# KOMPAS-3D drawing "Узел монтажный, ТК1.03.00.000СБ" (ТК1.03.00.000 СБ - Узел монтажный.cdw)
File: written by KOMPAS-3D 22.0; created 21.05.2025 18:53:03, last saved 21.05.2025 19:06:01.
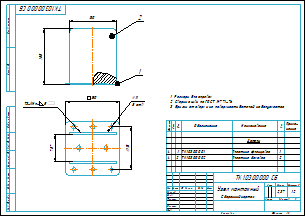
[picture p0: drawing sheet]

Sheet 1: A3, landscape

Document properties: Автор: TC; Масса: 2.373543; Полное имя файла: Узел монтажный.a3d

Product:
- Part/product: Узел монтажный  | designation ТК1.03.00.000СБ
    Масса: 2.373543
    Форматы листов документа: A3
  - Component [detail]: Пластина фланцевая  | designation ТК1.03.00.001  | qty 1  | pos. 1  | Масса: 0.815547; Форматы листов документа: A4; source file: Пластина фланцевая _ 5.cdw, Пластина фланцевая.m3d, ТК1.03.00.001 - Пластина фланцевая.cdw
  - Component [detail]: Пластина боковая  | designation ТК1.03.00.002  | qty 2  | pos. 2  | Материал: Сталь 09Г2С ГОСТ 19281-2014 (density 7850 kg/m3); Масса: 0.778998; Форматы листов документа: A4; source file: Пластина боковая _5.cdw, Пластина боковая.cdw, Пластина боковая.m3d
- Component: Обозначение стандартного шва по ГОСТ  | designation ГОСТ 14771-76-Т3-ИНп-@+34~5  | additional columns: 0; 1; 0; 0; 0; ГОСТ 14771-76-Т3-ИНп-@+34~5; ГОСТ 14771-76-Т3-ИНп-@+34~5; 0

Title block, sheet 1: Наименование: Узел монтажный / Сборочный чертеж; Масса: 2,37; Количество листов документа: 1; Форматы листов документа: A3; stored path: D:\Работа\2025\5. Май\Задание №6 - Тележка для крыши\3Д\Узел монтажный\Узел монтажный _ ТК1.03.00.000 СБ.cdw

Views: Вид 1, Местный разрез 1, Спереди, Проекционный вид 2
Referenced files in D:\Работа\2025\5. Май\Задание №6 - Тележка для крыши\3Д\Узел монтажный\: Пластина боковая.m3d, Пластина фланцевая.m3d, Узел монтажный.a3d, Пластина фланцевая _ 5.cdw, ТК1.03.00.001 - Пластина фланцевая.cdw, Пластина боковая _5.cdw, Пластина боковая.cdw
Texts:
  ТК1.03.00.000
  Т3-ИНп- 5
  ТК1.03.00.001
  Пластина фланцевая
  ТК1.03.00.002
  Пластина боковая
  BOSimple***Material:4ccf0190-16b6-4223-9222-aa108d28a442
  ТК1.03.00.001 Пластина фланцевая
  ТК1.03.00.002 Пластина боковая
  ТК1.03.00.000
  ТК1.03.00.000 СБ Узел монтажный
Dimensions and other numbers on the sheet: 155; 130; 2; 1; 75; 150; 118; 11; 8 отв.; 1:2; 2,37

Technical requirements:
  Размеры для справок.
  Сварные швы по ГОСТ 14771-76.
  Брызги от сварки на поверхности деталей не допускаются.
